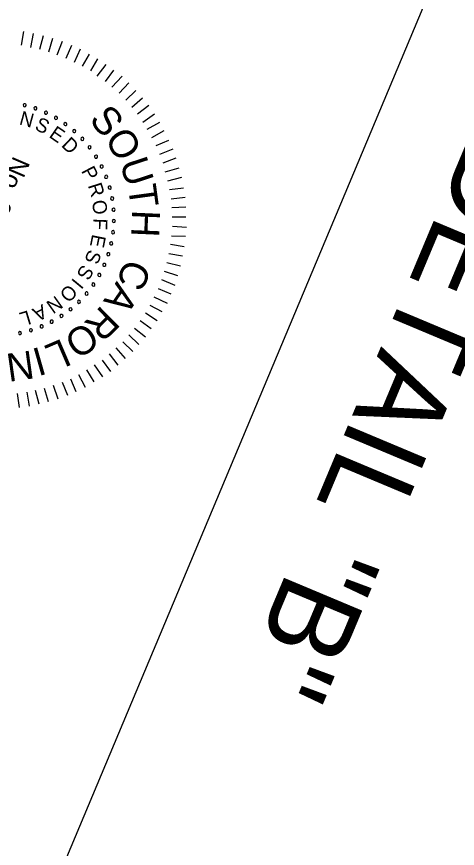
# Model space of a CAD drawing. Extents: x 1968564 to 1968711, y 796599 to 796794.
# Drawn here: x 1968589.2 to 1968596.99, y 796662.05 to 796676.76 of the extents above; entities that cross this region are included whole.
import ezdxf

# ---------------------------------------------------------------- set-up
doc = ezdxf.new("R2010")
doc.units = 0
doc.layers.add('BR_BORDER LINES', color=7, linetype='Continuous')
doc.layers.add('BR_TEXT', color=7, linetype='Continuous')

msp = doc.modelspace()

# ---------------------------------------------------------------- linework, layer by layer
at = {"layer": 'BR_BORDER LINES'}
msp.add_line((1968596.513, 796677.23), (1968588.212, 796657.44), dxfattribs=at)
at = {"layer": 'BR_TEXT'}
for p, q in [((1968589.284, 796676.248), (1968589.327, 796676.495)), ((1968589.45, 796676.207), (1968589.498, 796676.458)), ((1968589.611, 796676.182), (1968589.673, 796676.421)), ((1968589.769, 796676.133), (1968589.838, 796676.372)), ((1968589.915, 796676.081), (1968590.011, 796676.321)), ((1968590.076, 796676.02), (1968590.175, 796676.25)), ((1968590.224, 796675.949), (1968590.326, 796676.185)), ((1968590.366, 796675.877), (1968590.488, 796676.093)), ((1968590.51, 796675.796), (1968590.635, 796676.008)), ((1968590.626, 796675.702), (1968590.782, 796675.907)), ((1968590.77, 796675.61), (1968590.92, 796675.811)), ((1968590.884, 796675.509), (1968591.063, 796675.701)), ((1968591.013, 796675.401), (1968591.184, 796675.582)), ((1968591.128, 796675.277), (1968591.31, 796675.449)), ((1968591.236, 796675.156), (1968591.427, 796675.321)), ((1968591.335, 796675.039), (1968591.537, 796675.187)), ((1968591.433, 796674.892), (1968591.638, 796675.039)), ((1968591.507, 796674.767), (1968591.73, 796674.888)), ((1968591.589, 796674.62), (1968591.809, 796674.742)), ((1968591.666, 796674.478), (1968591.89, 796674.573)), ((1968591.734, 796674.322), (1968591.965, 796674.417)), ((1968591.789, 796674.172), (1968592.019, 796674.256)), ((1968591.829, 796674.012), (1968592.076, 796674.082)), ((1968591.871, 796673.849), (1968592.119, 796673.914)), ((1968591.901, 796673.701), (1968592.148, 796673.73)), ((1968591.934, 796673.534), (1968592.181, 796673.562)), ((1968591.946, 796673.38), (1968592.193, 796673.39)), ((1968591.951, 796673.217), (1968592.194, 796673.217)), ((1968591.953, 796673.048), (1968592.201, 796673.035)), ((1968591.938, 796672.882), (1968592.184, 796672.874)), ((1968591.919, 796672.734), (1968592.164, 796672.688)), ((1968591.892, 796672.566), (1968592.132, 796672.526)), ((1968591.858, 796672.409), (1968592.097, 796672.347)), ((1968591.811, 796672.257), (1968592.042, 796672.177)), ((1968591.759, 796672.108), (1968591.995, 796672.006)), ((1968591.702, 796671.949), (1968591.929, 796671.852)), ((1968591.626, 796671.799), (1968591.86, 796671.691)), ((1968591.553, 796671.655), (1968591.77, 796671.543)), ((1968591.476, 796671.519), (1968591.684, 796671.385)), ((1968591.384, 796671.383), (1968591.58, 796671.239)), ((1968591.281, 796671.248), (1968591.481, 796671.095)), ((1968591.185, 796671.129), (1968591.363, 796670.959)), ((1968591.076, 796671.004), (1968591.256, 796670.833)), ((1968590.836, 796670.793), (1968590.992, 796670.592)), ((1968590.956, 796670.898), (1968591.117, 796670.71)), ((1968590.71, 796670.683), (1968590.859, 796670.481)), ((1968590.437, 796670.508), (1968590.566, 796670.296)), ((1968590.569, 796670.598), (1968590.715, 796670.389)), ((1968590.15, 796670.352), (1968590.246, 796670.124)), ((1968590.291, 796670.429), (1968590.411, 796670.202)), ((1968589.686, 796670.185), (1968589.755, 796669.953)), ((1968589.846, 796670.236), (1968589.926, 796669.996)), ((1968590.004, 796670.291), (1968590.097, 796670.064)), ((1968589.211, 796670.089), (1968589.244, 796669.844)), ((1968589.382, 796670.113), (1968589.42, 796669.869)), ((1968589.525, 796670.149), (1968589.593, 796669.907))]:
    msp.add_line(p, q, dxfattribs=at)
for centre, start, end in [((1968589.342, 796675.189), 166.4652, 346.4652), ((1968589.342, 796675.189), 346.4652, 166.4652), ((1968589.533, 796675.133), 160.9267, 340.9267), ((1968589.533, 796675.133), 340.9267, 160.9267), ((1968589.718, 796675.058), 155.3882, 335.3882), ((1968589.718, 796675.058), 335.3882, 155.3882), ((1968589.895, 796674.966), 149.8498, 329.8498), ((1968589.895, 796674.966), 329.8498, 149.8498), ((1968590.062, 796674.857), 144.3113, 324.3113), ((1968590.062, 796674.857), 324.3113, 144.3113), ((1968590.218, 796674.733), 138.7728, 318.7728), ((1968590.218, 796674.733), 318.7728, 138.7728), ((1968590.361, 796674.594), 133.2344, 313.2344), ((1968590.361, 796674.594), 313.2344, 133.2344), ((1968590.49, 796674.443), 127.6959, 307.6959), ((1968590.49, 796674.443), 307.6959, 127.6959), ((1968590.604, 796674.279), 122.1575, 302.1575), ((1968590.604, 796674.279), 302.1575, 122.1575), ((1968590.702, 796674.105), 116.619, 296.619), ((1968590.702, 796674.105), 296.619, 116.619), ((1968590.782, 796673.923), 111.0805, 291.0805), ((1968590.782, 796673.923), 291.0805, 111.0805), ((1968590.844, 796673.733), 105.5421, 285.5421), ((1968590.844, 796673.733), 285.5421, 105.5421), ((1968590.888, 796673.539), 100.0036, 280.0036), ((1968590.888, 796673.539), 280.0036, 100.0036), ((1968590.912, 796673.341), 94.4652, 274.4652), ((1968590.912, 796673.341), 274.4652, 94.4652), ((1968590.918, 796673.142), 88.9267, 268.9267), ((1968590.918, 796673.142), 268.9267, 88.9267), ((1968590.904, 796672.943), 83.3882, 263.3882), ((1968590.904, 796672.943), 263.3882, 83.3882), ((1968590.871, 796672.746), 77.8498, 257.8498), ((1968590.871, 796672.746), 257.8498, 77.8498), ((1968590.82, 796672.554), 72.3113, 252.3113), ((1968590.82, 796672.554), 252.3113, 72.3113), ((1968590.75, 796672.367), 66.7728, 246.7728), ((1968590.75, 796672.367), 246.7728, 66.7728), ((1968590.662, 796672.188), 61.2344, 241.2344), ((1968590.662, 796672.188), 241.2344, 61.2344), ((1968590.557, 796672.019), 55.6959, 235.6959), ((1968590.557, 796672.019), 235.6959, 55.6959), ((1968590.437, 796671.86), 50.1575, 230.1575), ((1968590.437, 796671.86), 230.1575, 50.1575), ((1968590.302, 796671.713), 44.619, 224.619), ((1968590.302, 796671.713), 224.619, 44.619), ((1968589.992, 796671.463), 33.5421, 213.5421), ((1968590.153, 796671.581), 39.0805, 219.0805), ((1968590.153, 796671.581), 219.0805, 39.0805), ((1968589.82, 796671.361), 28.0036, 208.0036), ((1968589.82, 796671.361), 208.0036, 28.0036), ((1968589.992, 796671.463), 213.5421, 33.5421), ((1968589.452, 796671.21), 16.9267, 196.9267), ((1968589.452, 796671.21), 196.9267, 16.9267), ((1968589.64, 796671.277), 22.4652, 202.4652), ((1968589.64, 796671.277), 202.4652, 22.4652), ((1968589.259, 796671.161), 11.3882, 191.3882), ((1968589.259, 796671.161), 191.3882, 11.3882)]:
    msp.add_arc(centre, 0.028, start, end, dxfattribs=at)

# ---------------------------------------------------------------- texts
for s, height, rotation, p in [('N', 0.249, 344.5792, (1968589.232, 796674.853)), ('S', 0.496, 310.4972, (1968590.466, 796674.923)), ('S', 0.249, 335.032, (1968589.504, 796674.765)), ('E', 0.249, 325.4848, (1968589.757, 796674.634)), ('O', 0.496, 299.2727, (1968590.748, 796674.608)), ('D', 0.249, 316.2825, (1968589.977, 796674.47)), ('DETAIL "B"', 1.5, 247.246, (1968597.198, 796674.631)), ('No. 29964', 0.327, 246.7728, (1968589.144, 796674.304)), ('U', 0.496, 288.0483, (1968591.016, 796674.172)), ('P', 0.249, 297.1881, (1968590.336, 796674.029)), ('R', 0.249, 287.6409, (1968590.455, 796673.771)), ('T', 0.496, 277.7452, (1968591.167, 796673.757)), ('O', 0.249, 278.0937, (1968590.53, 796673.496)), ('H', 0.496, 267.6097, (1968591.243, 796673.344)), ('F', 0.249, 267.8587, (1968590.559, 796673.192)), ('E', 0.249, 258.6564, (1968590.538, 796672.918)), ('S', 0.249, 249.454, (1968590.474, 796672.65)), ('C', 0.496, 246.7942, (1968591.142, 796672.5)), ('S', 0.249, 239.9068, (1968590.363, 796672.388)), ('I', 0.249, 230.3596, (1968590.21, 796672.147)), ('A', 0.496, 235.4441, (1968590.972, 796672.087)), ('O', 0.249, 225.6852, (1968590.121, 796672.04)), ('N', 0.249, 215.4502, (1968589.897, 796671.831)), ('A', 0.249, 205.903, (1968589.658, 796671.676)), ('L', 0.249, 196.7006, (1968589.407, 796671.565)), ('R', 0.496, 224.6804, (1968590.708, 796671.664)), ('O', 0.496, 213.8329, (1968590.43, 796671.38)), ('I', 0.496, 195.9073, (1968589.621, 796670.922)), ('L', 0.496, 203.1948, (1968590.006, 796671.07)), ('N', 0.496, 187.9497, (1968589.466, 796670.854))]:
    msp.add_text(s, height=height, rotation=rotation, dxfattribs=at).set_placement(p)

doc.saveas('drawing.dxf')
